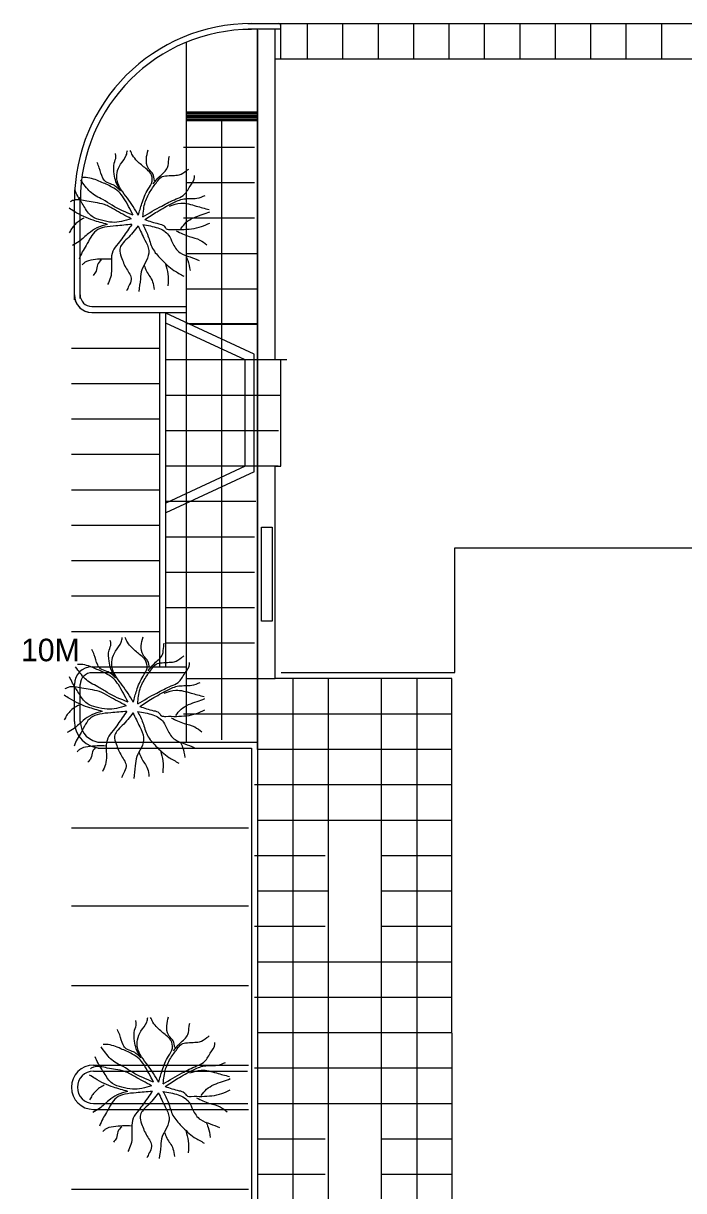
# Model space of a CAD drawing. Extents: x 6711323 to 6714641, y 1869258 to 1871224.
# Drawn here: x 6712585.5 to 6712660.1, y 1870013.3 to 1870145.1 of the extents above; entities that cross this region are included whole.
import ezdxf

# ---------------------------------------------------------------- set-up
doc = ezdxf.new("R2010")
doc.units = 0
for name, color, linetype in [('AsBuilt Chng(62)', 7, 'Continuous'), ('Curb Gutter (21)', 7, 'Continuous'), ('Front Align (17)', 7, 'Continuous'), ('HQ Changes (61)', 7, 'Continuous'), ('Layout Notes(23)', 7, 'Continuous'), ('Pave Edges (20)', 7, 'Continuous'), ('Profile Grid (9)', 7, 'Continuous'), ('Ramp Anno (14)', 7, 'Continuous'), ('Undefined (Lv19)', 7, 'Continuous')]:
    doc.layers.add(name, color=color, linetype=linetype)

msp = doc.modelspace()

# ---------------------------------------------------------------- linework, layer by layer
at = {"layer": 'AsBuilt Chng(62)'}
for p, q in [((6712613.97, 1870107.12), (6712613.97, 1870141.12)), ((6712613.97, 1870141.12), (6712694.64, 1870141.12)), ((6712614.64, 1870107.12), (6712613.97, 1870107.12)), ((6712614.64, 1870095.12), (6712614.64, 1870107.12)), ((6712613.97, 1870071.13), (6712613.97, 1870095.12)), ((6712613.97, 1870095.12), (6712614.64, 1870095.12)), ((6712634.26, 1870071.82), (6712634.26, 1870085.9)), ((6712634.26, 1870085.9), (6712695.06, 1870085.9)), ((6712633.95, 1870071.13), (6712613.97, 1870071.13)), ((6712614.66, 1870071.82), (6712634.26, 1870071.82))]:
    msp.add_line(p, q, dxfattribs=at)
msp.add_lwpolyline([(6712613.64, 1870077.62), (6712612.45, 1870077.62), (6712612.45, 1870088.24), (6712613.64, 1870088.24)], close=True, dxfattribs=at)
msp.add_lwpolyline([(6712714.64, 1869849.79), (6712639.97, 1869849.79), (6712639.97, 1869957.79), (6712625.97, 1869957.79), (6712625.97, 1869991.12), (6712633.97, 1869991.12), (6712633.95, 1870071.13)], dxfattribs=at)
at = {"layer": 'Curb Gutter (21)'}
for p, q in [((6712610.91, 1870145.12), (6712678, 1870145.12)), ((6712614.57, 1870144.47), (6712611.36, 1870144.47)), ((6712613.97, 1870141.12), (6712613.97, 1870144.47)), ((6712614.61, 1870141.12), (6712614.61, 1870145.12)), ((6712591.31, 1870113.92), (6712591.31, 1870125.13)), ((6712591.97, 1870114.08), (6712591.97, 1870125.5)), ((6712593.28, 1870113.15), (6712603.98, 1870113.15)), ((6712593.28, 1870112.49), (6712601.28, 1870112.49)), ((6712593.31, 1870112.47), (6712603.98, 1870112.47)), ((6712600.97, 1870072.47), (6712600.97, 1870112.47)), ((6712593.3, 1870072.47), (6712603.97, 1870072.47)), ((6712591.3, 1870066.29), (6712591.3, 1870070.47)), ((6712593.97, 1870063.29), (6712611.31, 1870063.29)), ((6712611.31, 1870063.29), (6712611.31, 1869945.47)), ((6712593.47, 1870027.47), (6712610.97, 1870027.47)), ((6712593.47, 1870022.47), (6712610.97, 1870022.47))]:
    msp.add_line(p, q, dxfattribs=at)
for centre, radius, start, end in [((6712611.31, 1870125.13), 20, 90, 180), ((6712611.31, 1870125.13), 19.33, 90, 180), ((6712614.36, 1870144.87), 0.25, 360, 90), ((6712593.28, 1870114.49), 2, 180, 270), ((6712593.31, 1870114.47), 2, 180, 270), ((6712593.28, 1870114.49), 1.33, 180, 270), ((6712593.3, 1870070.47), 2, 90, 180), ((6712594.3, 1870066.29), 3, 180, 270), ((6712593.47, 1870024.97), 2.5, 90, 270)]:
    msp.add_arc(centre, radius, start, end, dxfattribs=at)
at = {"layer": 'Front Align (17)'}
for p, q in [((6712590.97, 1870108.47), (6712600.97, 1870108.47)), ((6712590.97, 1870104.47), (6712600.97, 1870104.47)), ((6712590.97, 1870100.47), (6712600.97, 1870100.47)), ((6712590.97, 1870096.47), (6712600.97, 1870096.47)), ((6712590.97, 1870092.47), (6712600.97, 1870092.47)), ((6712590.97, 1870088.47), (6712600.97, 1870088.47)), ((6712590.97, 1870084.47), (6712600.97, 1870084.47)), ((6712590.97, 1870080.47), (6712600.97, 1870080.47)), ((6712590.97, 1870076.47), (6712600.97, 1870076.47)), ((6712590.97, 1870054.29), (6712610.97, 1870054.29)), ((6712590.97, 1870045.47), (6712610.97, 1870045.47)), ((6712590.97, 1870036.47), (6712610.97, 1870036.47)), ((6712590.97, 1870013.47), (6712610.97, 1870013.47))]:
    msp.add_line(p, q, dxfattribs=at)
at = {"layer": 'HQ Changes (61)'}
for p, q in [((6712613.97, 1870107.14), (6712613.97, 1870141.12)), ((6712613.97, 1870141.12), (6712694.64, 1870141.12)), ((6712613.97, 1870093.98), (6712613.97, 1870095.07)), ((6712613.97, 1870071.13), (6712613.97, 1870093.79)), ((6712633.95, 1870071.13), (6712613.97, 1870071.13))]:
    msp.add_line(p, q, dxfattribs=at)
msp.add_lwpolyline([(6712714.64, 1869849.79), (6712639.97, 1869849.79), (6712639.97, 1869957.79), (6712625.97, 1869957.79), (6712625.97, 1869991.12), (6712633.97, 1869991.12), (6712633.95, 1870071.13)], dxfattribs=at)
at = {"layer": 'Layout Notes(23)'}
msp.add_line((6712615.31, 1870107.12), (6712614.64, 1870107.12), dxfattribs=at)
at = {"layer": 'Pave Edges (20)'}
for p, q in [((6712611.5, 1870144.47), (6712610.94, 1870144.47)), ((6712617.64, 1870141.12), (6712617.64, 1870145.14)), ((6712621.64, 1870141.12), (6712621.64, 1870145.12)), ((6712625.64, 1870141.12), (6712625.64, 1870145.14)), ((6712629.64, 1870141.12), (6712629.64, 1870145.12)), ((6712633.64, 1870141.12), (6712633.64, 1870145.14)), ((6712637.64, 1870141.12), (6712637.64, 1870145.12)), ((6712641.64, 1870141.12), (6712641.64, 1870145.14)), ((6712645.64, 1870141.12), (6712645.64, 1870145.12)), ((6712649.64, 1870141.12), (6712649.64, 1870145.14)), ((6712653.64, 1870141.12), (6712653.64, 1870145.12)), ((6712657.64, 1870141.12), (6712657.64, 1870145.14)), ((6712611.98, 1870134.96), (6712603.98, 1870134.96)), ((6712611.98, 1870134.79), (6712603.98, 1870134.79)), ((6712611.98, 1870134.62), (6712603.98, 1870134.62)), ((6712611.98, 1870134.46), (6712603.98, 1870134.46)), ((6712611.98, 1870134.29), (6712603.98, 1870134.29)), ((6712611.98, 1870134.12), (6712603.98, 1870134.12)), ((6712607.97, 1870064.22), (6712607.97, 1870134.12)), ((6712611.64, 1870131.12), (6712603.64, 1870131.12)), ((6712611.64, 1870123.12), (6712603.64, 1870123.12)), ((6712611.97, 1870115.12), (6712603.97, 1870115.12)), ((6712611.97, 1870111.21), (6712603.97, 1870111.21)), ((6712613.66, 1870107.12), (6712601.64, 1870107.12)), ((6712614.35, 1870099.13), (6712601.64, 1870099.13)), ((6712611.79, 1870091.12), (6712601.64, 1870091.12)), ((6712611.64, 1870083.12), (6712601.64, 1870083.12)), ((6712611.64, 1870075.12), (6712601.64, 1870075.12)), ((6712615.97, 1870071.13), (6712615.97, 1869794.74)), ((6712629.97, 1870071.13), (6712629.97, 1869991.12)), ((6712633.97, 1870067.12), (6712603.64, 1870067.12)), ((6712633.97, 1870059.12), (6712611.64, 1870059.12)), ((6712619.64, 1870051.12), (6712611.64, 1870051.12)), ((6712633.97, 1870051.12), (6712625.97, 1870051.12)), ((6712619.64, 1870043.12), (6712611.64, 1870043.12)), ((6712633.97, 1870043.12), (6712625.97, 1870043.12)), ((6712633.97, 1870035.12), (6712611.64, 1870035.12)), ((6712633.97, 1870027.12), (6712611.64, 1870027.12)), ((6712619.64, 1870019.12), (6712611.97, 1870019.12)), ((6712633.97, 1870019.12), (6712625.97, 1870019.12))]:
    msp.add_line(p, q, dxfattribs=at)
at = {"layer": 'Profile Grid (9)'}
for points in [[(6712596.52, 1870126.23), (6712596, 1870127.25), (6712595.81, 1870128.09), (6712595.81, 1870129.35), (6712596, 1870130.07), (6712595.94, 1870130.43)], [(6712598.53, 1870123.47), (6712597.3, 1870125.39), (6712596.13, 1870127.37), (6712596.13, 1870128.27), (6712596.52, 1870129.23), (6712597.17, 1870130.25), (6712597.3, 1870130.79)], [(6712598.53, 1870123.47), (6712598.92, 1870124.79), (6712599.63, 1870126.41), (6712600.09, 1870127.31), (6712599.89, 1870128.21), (6712599.37, 1870128.75), (6712598.4, 1870129.59), (6712597.88, 1870130.25), (6712597.62, 1870130.79)], [(6712600.34, 1870127.37), (6712600.15, 1870128.15), (6712600.02, 1870128.33), (6712599.63, 1870128.81), (6712599.44, 1870129.83), (6712599.63, 1870130.85)], [(6712600.21, 1870127.01), (6712600.93, 1870127.85), (6712601.83, 1870128.87), (6712601.96, 1870129.77), (6712602.03, 1870130.13)], [(6712596.52, 1870126.23), (6712595.55, 1870126.95), (6712594.84, 1870127.25), (6712594.51, 1870127.67), (6712594.12, 1870128.81), (6712593.87, 1870129.41)], [(6712599.05, 1870123.29), (6712599.31, 1870124.97), (6712599.96, 1870126.29), (6712600.73, 1870127.37), (6712601.25, 1870127.85), (6712601.58, 1870127.91), (6712602.42, 1870127.97), (6712603.13, 1870128.03), (6712603.97, 1870128.51), (6712604.23, 1870128.69)], [(6712597.95, 1870123.47), (6712595.56, 1870124.59), (6712594.53, 1870125.23), (6712593.75, 1870125.63), (6712592.54, 1870126.74), (6712592.03, 1870127.46)], [(6712597.95, 1870123.47), (6712596.85, 1870125.45), (6712596.33, 1870126.11), (6712595.55, 1870126.65), (6712594.25, 1870127.25), (6712592.63, 1870127.73), (6712592.25, 1870127.73)], [(6712599.05, 1870123.29), (6712601.17, 1870124.51), (6712602.81, 1870125.31), (6712603.59, 1870125.7), (6712604.37, 1870126.74), (6712604.88, 1870127.78), (6712604.88, 1870127.94)], [(6712597.72, 1870123.07), (6712595.56, 1870122.67), (6712594.36, 1870122.91), (6712593.32, 1870123.31), (6712592.37, 1870124.51), (6712591.68, 1870125.63), (6712591.34, 1870126.34)], [(6712597.72, 1870123.07), (6712595.82, 1870124.11), (6712594.7, 1870124.67), (6712593.67, 1870124.91), (6712592.72, 1870125.07), (6712591.16, 1870125.15), (6712590.82, 1870124.99)], [(6712599.27, 1870122.99), (6712600.66, 1870123.87), (6712602.38, 1870124.83), (6712603.68, 1870125.31), (6712605.14, 1870125.39), (6712606.09, 1870125.7)], [(6712602.04, 1870124.51), (6712603.33, 1870124.83), (6712605.06, 1870124.51), (6712606.52, 1870124.11)], [(6712595.05, 1870122.43), (6712593.41, 1870122.91), (6712592.37, 1870123.31), (6712591.34, 1870123.87), (6712590.73, 1870124.27)], [(6712603.33, 1870121.95), (6712603.93, 1870122.67), (6712605.75, 1870123.55), (6712606.61, 1870123.87)], [(6712592.37, 1870123.15), (6712591.85, 1870122.83), (6712590.99, 1870121.95), (6712590.73, 1870121.47)], [(6712595.05, 1870122.43), (6712593.84, 1870122.03), (6712592.89, 1870121.39), (6712591.85, 1870120.52), (6712591.08, 1870120.04)], [(6712597.81, 1870122.43), (6712596, 1870122.27), (6712594.7, 1870122.11), (6712593.75, 1870121.71), (6712593.15, 1870120.99), (6712592.63, 1870120.04), (6712592.2, 1870119.32), (6712591.85, 1870118.52)], [(6712597.81, 1870122.43), (6712597.29, 1870121.71), (6712596.25, 1870120.28), (6712595.65, 1870119.4), (6712595.48, 1870118.36), (6712595.39, 1870116.44), (6712595.05, 1870115.64)], [(6712598.5, 1870122.27), (6712597.29, 1870120.83), (6712596.69, 1870120.2), (6712596.43, 1870119.64), (6712596.6, 1870118.76), (6712597.2, 1870117.4), (6712597.72, 1870116.2), (6712597.46, 1870115.48), (6712597.2, 1870114.93)], [(6712598.5, 1870122.27), (6712599.27, 1870120.67), (6712599.71, 1870119.48), (6712599.45, 1870118.36), (6712598.93, 1870117.32), (6712598.76, 1870116.28), (6712598.58, 1870114.85)], [(6712599.02, 1870122.43), (6712599.62, 1870121.15), (6712600.14, 1870119.72), (6712601.09, 1870118.52), (6712602.55, 1870117.24), (6712603.68, 1870116.6)], [(6712599.02, 1870122.43), (6712600.74, 1870122.03), (6712601.43, 1870121.71), (6712601.95, 1870121.23), (6712602.38, 1870120.36), (6712603.24, 1870119.24), (6712604.37, 1870118.76), (6712605.4, 1870118.36)], [(6712599.27, 1870122.99), (6712600.83, 1870122.51), (6712601.43, 1870122.27), (6712601.69, 1870121.95), (6712602.21, 1870121.87), (6712603.42, 1870121.87), (6712605.66, 1870122.19), (6712606.61, 1870122.59)], [(6712602.81, 1870121.71), (6712604.28, 1870121.07), (6712605.49, 1870120.67), (6712606.26, 1870120.12)], [(6712595.48, 1870118.52), (6712593.41, 1870118.44), (6712592.46, 1870118.12), (6712592.2, 1870117.88)], [(6712594.36, 1870118.44), (6712593.92, 1870117.88), (6712593.75, 1870117.16), (6712593.41, 1870116.68)], [(6712603.85, 1870119), (6712604.11, 1870118.36), (6712604.37, 1870117.24)], [(6712599.19, 1870117.8), (6712599.45, 1870117.16), (6712600.14, 1870115.96), (6712600.31, 1870115.09)], [(6712601.6, 1870117.96), (6712601.86, 1870116.84), (6712601.86, 1870115.48)], [(6712595.95, 1870071.23), (6712595.43, 1870072.25), (6712595.23, 1870073.09), (6712595.23, 1870074.35), (6712595.43, 1870075.06), (6712595.36, 1870075.42)], [(6712597.96, 1870068.47), (6712596.72, 1870070.39), (6712595.56, 1870072.37), (6712595.56, 1870073.27), (6712595.95, 1870074.23), (6712596.59, 1870075.24), (6712596.72, 1870075.78)], [(6712597.96, 1870068.47), (6712598.34, 1870069.79), (6712599.06, 1870071.41), (6712599.51, 1870072.31), (6712599.32, 1870073.21), (6712598.8, 1870073.75), (6712597.83, 1870074.59), (6712597.31, 1870075.24), (6712597.05, 1870075.78)], [(6712599.77, 1870072.37), (6712599.58, 1870073.15), (6712599.45, 1870073.33), (6712599.06, 1870073.81), (6712598.86, 1870074.83), (6712599.06, 1870075.84)], [(6712599.64, 1870072.01), (6712600.35, 1870072.85), (6712601.26, 1870073.87), (6712601.39, 1870074.77), (6712601.45, 1870075.12)], [(6712595.95, 1870071.23), (6712594.97, 1870071.95), (6712594.26, 1870072.25), (6712593.94, 1870072.67), (6712593.55, 1870073.81), (6712593.29, 1870074.41)], [(6712598.47, 1870068.29), (6712598.73, 1870069.97), (6712599.38, 1870071.29), (6712600.16, 1870072.37), (6712600.68, 1870072.85), (6712601, 1870072.91), (6712601.84, 1870072.97), (6712602.56, 1870073.03), (6712603.4, 1870073.51), (6712603.66, 1870073.69)], [(6712597.37, 1870068.47), (6712594.99, 1870069.58), (6712593.95, 1870070.22), (6712593.18, 1870070.62), (6712591.97, 1870071.74), (6712591.45, 1870072.46)], [(6712597.37, 1870068.47), (6712596.27, 1870070.45), (6712595.75, 1870071.11), (6712594.97, 1870071.65), (6712593.68, 1870072.25), (6712592.06, 1870072.73), (6712591.67, 1870072.73)], [(6712598.47, 1870068.29), (6712600.6, 1870069.5), (6712602.24, 1870070.3), (6712603.01, 1870070.7), (6712603.79, 1870071.74), (6712604.31, 1870072.78), (6712604.31, 1870072.94)], [(6712597.15, 1870068.07), (6712594.99, 1870067.67), (6712593.78, 1870067.91), (6712592.75, 1870068.31), (6712591.8, 1870069.5), (6712591.11, 1870070.62), (6712590.76, 1870071.34)], [(6712598.7, 1870067.99), (6712600.08, 1870068.87), (6712601.81, 1870069.82), (6712603.1, 1870070.3), (6712604.57, 1870070.38), (6712605.52, 1870070.7)], [(6712594.47, 1870067.43), (6712592.83, 1870067.91), (6712591.8, 1870068.31), (6712590.76, 1870068.87), (6712590.16, 1870069.27)], [(6712597.15, 1870068.07), (6712595.25, 1870069.11), (6712594.13, 1870069.66), (6712593.09, 1870069.9), (6712592.14, 1870070.06), (6712590.59, 1870070.14), (6712590.24, 1870069.98)], [(6712601.46, 1870069.5), (6712602.76, 1870069.82), (6712604.48, 1870069.5), (6712605.95, 1870069.11)], [(6712591.8, 1870068.15), (6712591.28, 1870067.83), (6712590.42, 1870066.95), (6712590.16, 1870066.47)], [(6712598.7, 1870067.99), (6712600.25, 1870067.51), (6712600.86, 1870067.27), (6712601.12, 1870066.95), (6712601.63, 1870066.87), (6712602.84, 1870066.87), (6712605.08, 1870067.19), (6712606.03, 1870067.59)], [(6712602.76, 1870066.95), (6712603.36, 1870067.67), (6712605.17, 1870068.55), (6712606.03, 1870068.87)], [(6712594.47, 1870067.43), (6712593.26, 1870067.03), (6712592.31, 1870066.39), (6712591.28, 1870065.51), (6712590.5, 1870065.03)], [(6712597.23, 1870067.43), (6712595.42, 1870067.27), (6712594.13, 1870067.11), (6712593.18, 1870066.71), (6712592.57, 1870065.99), (6712592.06, 1870065.03), (6712591.62, 1870064.31), (6712591.28, 1870063.52)], [(6712597.23, 1870067.43), (6712596.72, 1870066.71), (6712595.68, 1870065.27), (6712595.08, 1870064.39), (6712594.9, 1870063.36), (6712594.82, 1870061.44), (6712594.47, 1870060.64)], [(6712597.92, 1870067.27), (6712596.72, 1870065.83), (6712596.11, 1870065.19), (6712595.85, 1870064.63), (6712596.02, 1870063.76), (6712596.63, 1870062.4), (6712597.15, 1870061.2), (6712596.89, 1870060.48), (6712596.63, 1870059.92)], [(6712597.92, 1870067.27), (6712598.7, 1870065.67), (6712599.13, 1870064.47), (6712598.87, 1870063.36), (6712598.35, 1870062.32), (6712598.18, 1870061.28), (6712598.01, 1870059.84)], [(6712598.44, 1870067.43), (6712599.04, 1870066.15), (6712599.56, 1870064.71), (6712600.51, 1870063.52), (6712601.98, 1870062.24), (6712603.1, 1870061.6)], [(6712598.44, 1870067.43), (6712600.17, 1870067.03), (6712600.86, 1870066.71), (6712601.37, 1870066.23), (6712601.81, 1870065.35), (6712602.67, 1870064.24), (6712603.79, 1870063.76), (6712604.83, 1870063.36)], [(6712602.24, 1870066.71), (6712603.7, 1870066.07), (6712604.91, 1870065.67), (6712605.69, 1870065.11)], [(6712603.27, 1870064), (6712603.53, 1870063.36), (6712603.79, 1870062.24)], [(6712594.9, 1870063.52), (6712592.83, 1870063.44), (6712591.88, 1870063.12), (6712591.62, 1870062.88)], [(6712593.78, 1870063.44), (6712593.35, 1870062.88), (6712593.18, 1870062.16), (6712592.83, 1870061.68)], [(6712598.61, 1870062.8), (6712598.87, 1870062.16), (6712599.56, 1870060.96), (6712599.73, 1870060.08)], [(6712601.03, 1870062.96), (6712601.29, 1870061.84), (6712601.29, 1870060.48)], [(6712598.82, 1870028.31), (6712598.3, 1870029.33), (6712598.11, 1870030.17), (6712598.11, 1870031.43), (6712598.3, 1870032.15), (6712598.24, 1870032.51)], [(6712600.83, 1870025.55), (6712599.6, 1870027.47), (6712598.43, 1870029.45), (6712598.43, 1870030.35), (6712598.82, 1870031.31), (6712599.47, 1870032.33), (6712599.6, 1870032.87)], [(6712600.83, 1870025.55), (6712601.22, 1870026.87), (6712601.93, 1870028.49), (6712602.38, 1870029.39), (6712602.19, 1870030.29), (6712601.67, 1870030.83), (6712600.7, 1870031.67), (6712600.18, 1870032.33), (6712599.92, 1870032.87)], [(6712602.64, 1870029.45), (6712602.45, 1870030.23), (6712602.32, 1870030.41), (6712601.93, 1870030.89), (6712601.74, 1870031.91), (6712601.93, 1870032.93)], [(6712598.82, 1870028.31), (6712597.85, 1870029.03), (6712597.14, 1870029.33), (6712596.81, 1870029.75), (6712596.42, 1870030.89), (6712596.16, 1870031.49)], [(6712602.51, 1870029.09), (6712603.23, 1870029.93), (6712604.13, 1870030.95), (6712604.26, 1870031.85), (6712604.33, 1870032.21)], [(6712600.25, 1870025.55), (6712599.14, 1870027.53), (6712598.63, 1870028.19), (6712597.85, 1870028.73), (6712596.55, 1870029.33), (6712594.93, 1870029.81), (6712594.54, 1870029.81)], [(6712601.35, 1870025.37), (6712601.61, 1870027.05), (6712602.25, 1870028.37), (6712603.03, 1870029.45), (6712603.55, 1870029.93), (6712603.87, 1870029.99), (6712604.72, 1870030.05), (6712605.43, 1870030.11), (6712606.27, 1870030.59), (6712606.53, 1870030.77)], [(6712601.35, 1870025.37), (6712603.47, 1870026.59), (6712605.11, 1870027.39), (6712605.89, 1870027.78), (6712606.66, 1870028.82), (6712607.18, 1870029.86), (6712607.18, 1870030.02)], [(6712600.02, 1870025.15), (6712597.86, 1870024.75), (6712596.66, 1870024.99), (6712595.62, 1870025.39), (6712594.67, 1870026.59), (6712593.98, 1870027.7), (6712593.64, 1870028.42)], [(6712600.25, 1870025.55), (6712597.86, 1870026.67), (6712596.83, 1870027.31), (6712596.05, 1870027.7), (6712594.84, 1870028.82), (6712594.33, 1870029.54)], [(6712600.02, 1870025.15), (6712598.12, 1870026.19), (6712597, 1870026.75), (6712595.96, 1870026.99), (6712595.02, 1870027.15), (6712593.46, 1870027.23), (6712593.12, 1870027.07)], [(6712601.57, 1870025.07), (6712602.95, 1870025.95), (6712604.68, 1870026.91), (6712605.97, 1870027.39), (6712607.44, 1870027.47), (6712608.39, 1870027.78)], [(6712597.35, 1870024.51), (6712595.71, 1870024.99), (6712594.67, 1870025.39), (6712593.64, 1870025.95), (6712593.03, 1870026.35)], [(6712604.33, 1870026.59), (6712605.63, 1870026.91), (6712607.35, 1870026.59), (6712608.82, 1870026.19)], [(6712605.63, 1870024.03), (6712606.23, 1870024.75), (6712608.04, 1870025.63), (6712608.91, 1870025.95)], [(6712594.67, 1870025.23), (6712594.15, 1870024.91), (6712593.29, 1870024.03), (6712593.03, 1870023.55)], [(6712597.35, 1870024.51), (6712596.14, 1870024.11), (6712595.19, 1870023.47), (6712594.15, 1870022.59), (6712593.38, 1870022.12)], [(6712600.11, 1870024.51), (6712598.29, 1870024.35), (6712597, 1870024.19), (6712596.05, 1870023.79), (6712595.45, 1870023.07), (6712594.93, 1870022.12), (6712594.5, 1870021.4), (6712594.15, 1870020.6)], [(6712600.11, 1870024.51), (6712599.59, 1870023.79), (6712598.55, 1870022.36), (6712597.95, 1870021.48), (6712597.78, 1870020.44), (6712597.69, 1870018.52), (6712597.35, 1870017.72)], [(6712601.31, 1870024.51), (6712601.92, 1870023.23), (6712602.44, 1870021.8), (6712603.39, 1870020.6), (6712604.85, 1870019.32), (6712605.97, 1870018.68)], [(6712601.31, 1870024.51), (6712603.04, 1870024.11), (6712603.73, 1870023.79), (6712604.25, 1870023.31), (6712604.68, 1870022.43), (6712605.54, 1870021.32), (6712606.66, 1870020.84), (6712607.7, 1870020.44)], [(6712601.57, 1870025.07), (6712603.13, 1870024.59), (6712603.73, 1870024.35), (6712603.99, 1870024.03), (6712604.51, 1870023.95), (6712605.71, 1870023.95), (6712607.96, 1870024.27), (6712608.91, 1870024.67)], [(6712600.8, 1870024.35), (6712599.59, 1870022.91), (6712598.98, 1870022.28), (6712598.73, 1870021.72), (6712598.9, 1870020.84), (6712599.5, 1870019.48), (6712600.02, 1870018.28), (6712599.76, 1870017.56), (6712599.5, 1870017.01)], [(6712600.8, 1870024.35), (6712601.57, 1870022.75), (6712602, 1870021.56), (6712601.75, 1870020.44), (6712601.23, 1870019.4), (6712601.06, 1870018.36), (6712600.88, 1870016.93)], [(6712605.11, 1870023.79), (6712606.58, 1870023.15), (6712607.79, 1870022.75), (6712608.56, 1870022.2)], [(6712597.78, 1870020.6), (6712595.71, 1870020.52), (6712594.76, 1870020.2), (6712594.5, 1870019.96)], [(6712596.66, 1870020.52), (6712596.22, 1870019.96), (6712596.05, 1870019.24), (6712595.71, 1870018.76)], [(6712606.15, 1870021.08), (6712606.41, 1870020.44), (6712606.66, 1870019.32)], [(6712601.49, 1870019.88), (6712601.75, 1870019.24), (6712602.44, 1870018.04), (6712602.61, 1870017.17)], [(6712603.9, 1870020.04), (6712604.16, 1870018.92), (6712604.16, 1870017.56)]]:
    msp.add_spline(points, degree=3, dxfattribs=at)
at = {"layer": 'Undefined (Lv19)'}
for p, q in [((6712611.97, 1870063.12), (6712611.97, 1870144.47)), ((6712611.97, 1870144.38), (6712611.97, 1869794.74)), ((6712603.97, 1870063.95), (6712603.97, 1870143.02)), ((6712611.98, 1870135.12), (6712603.98, 1870135.12)), ((6712611.64, 1870127.12), (6712603.97, 1870127.12)), ((6712611.97, 1870119.12), (6712603.97, 1870119.12)), ((6712601.64, 1870072.47), (6712601.64, 1870112.47)), ((6712611.61, 1870107.76), (6712601.64, 1870112.39)), ((6712610.61, 1870107.12), (6712601.64, 1870111.29)), ((6712611.97, 1870111.12), (6712604.37, 1870111.12)), ((6712611.61, 1870094.49), (6712611.61, 1870107.76)), ((6712610.61, 1870095.12), (6712610.61, 1870107.12)), ((6712613.97, 1870107.12), (6712611.96, 1870107.12)), ((6712614.64, 1870103.12), (6712601.64, 1870103.12)), ((6712614.33, 1870095.12), (6712601.64, 1870095.12)), ((6712610.61, 1870095.12), (6712601.64, 1870090.96)), ((6712611.61, 1870094.49), (6712601.64, 1870089.86)), ((6712611.64, 1870087.12), (6712601.64, 1870087.12)), ((6712611.64, 1870079.12), (6712601.64, 1870079.12)), ((6712593.3, 1870071.81), (6712603.97, 1870071.81)), ((6712613.97, 1870071.12), (6712603.97, 1870071.12)), ((6712619.97, 1870071.13), (6712619.97, 1869841.79)), ((6712625.97, 1870071.13), (6712625.97, 1869991.12)), ((6712591.97, 1870066.29), (6712591.97, 1870070.47)), ((6712593.97, 1870063.95), (6712611.97, 1870063.95)), ((6712633.97, 1870063.12), (6712611.97, 1870063.12)), ((6712633.97, 1870055.12), (6712611.97, 1870055.12)), ((6712619.97, 1870047.12), (6712611.97, 1870047.12)), ((6712633.97, 1870047.12), (6712625.97, 1870047.12)), ((6712633.97, 1870039.12), (6712611.97, 1870039.12)), ((6712633.97, 1870031.12), (6712611.97, 1870031.12)), ((6712593.47, 1870026.81), (6712610.87, 1870026.81)), ((6712593.47, 1870023.14), (6712610.9, 1870023.14)), ((6712633.97, 1870023.12), (6712611.97, 1870023.12)), ((6712619.64, 1870015.12), (6712611.97, 1870015.12)), ((6712633.97, 1870015.12), (6712625.97, 1870015.12))]:
    msp.add_line(p, q, dxfattribs=at)
for centre, radius, start, end in [((6712593.3, 1870070.47), 1.33, 90, 180), ((6712594.3, 1870066.29), 2.33, 180, 270), ((6712593.47, 1870024.97), 1.83, 90, 270)]:
    msp.add_arc(centre, radius, start, end, dxfattribs=at)

# ---------------------------------------------------------------- texts
at = {"layer": 'Ramp Anno (14)'}
msp.add_text('10M', height=2.55, dxfattribs=at).set_placement((6712585.28, 1870073.09))

doc.saveas('drawing.dxf')
